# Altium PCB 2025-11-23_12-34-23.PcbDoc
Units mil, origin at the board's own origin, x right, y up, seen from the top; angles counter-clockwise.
Board outline 2370 x 1275 mil, 4 copper layers (Top Layer, MidLayer1, MidLayer2, Bottom Layer); 33 components, 22 nets, 92 pads, 279 vias.
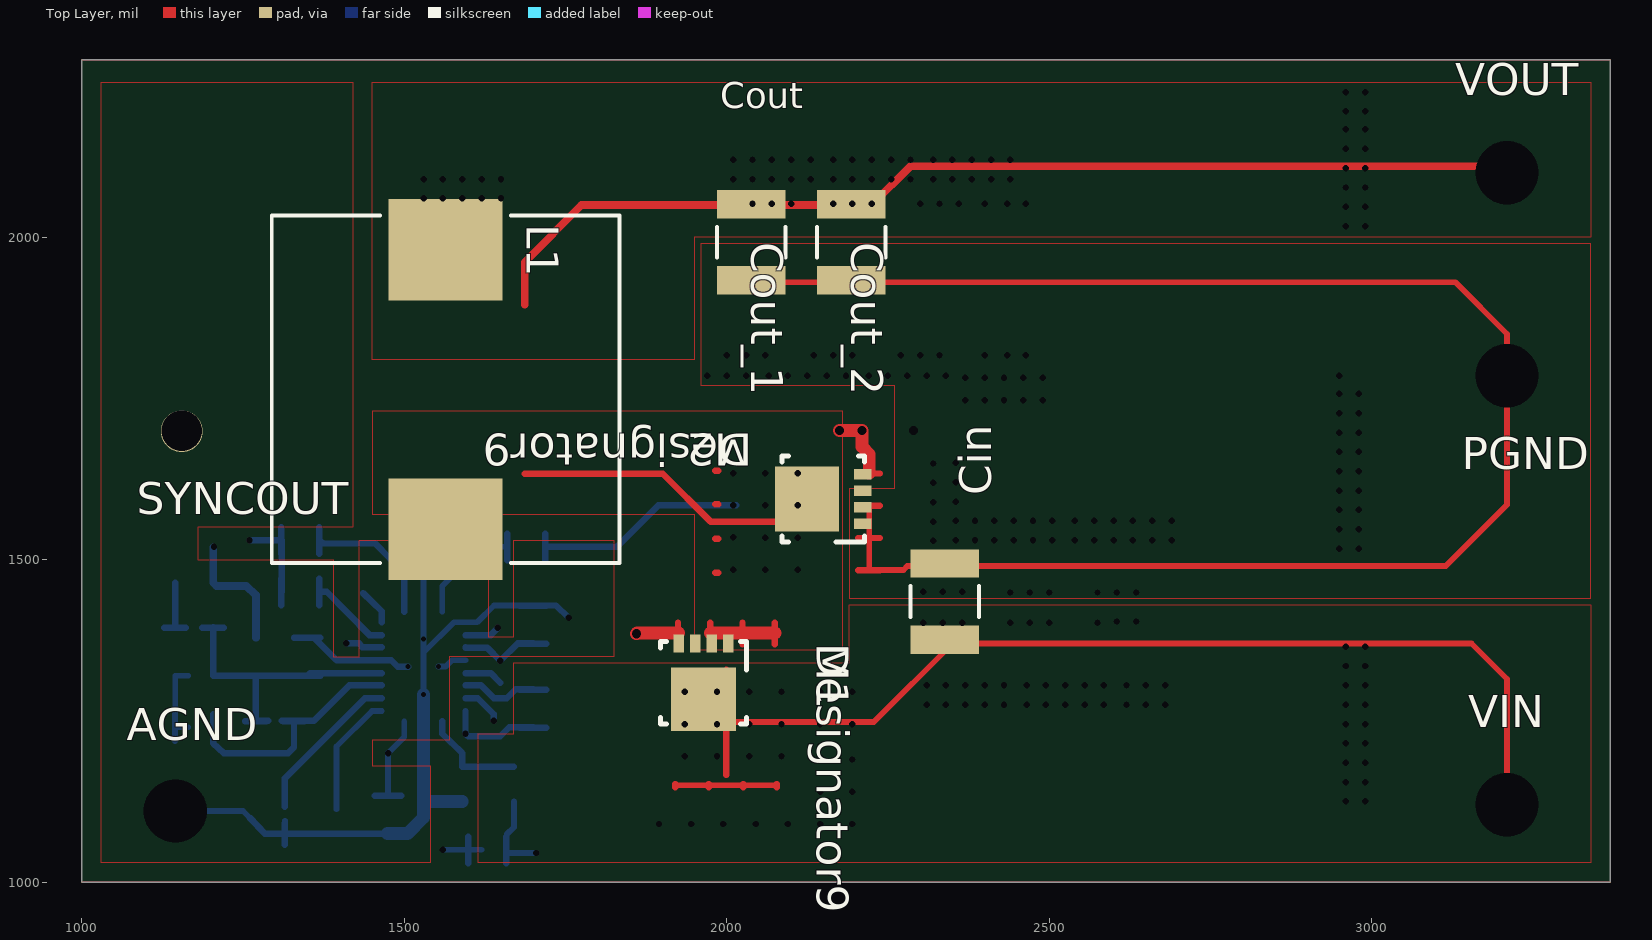
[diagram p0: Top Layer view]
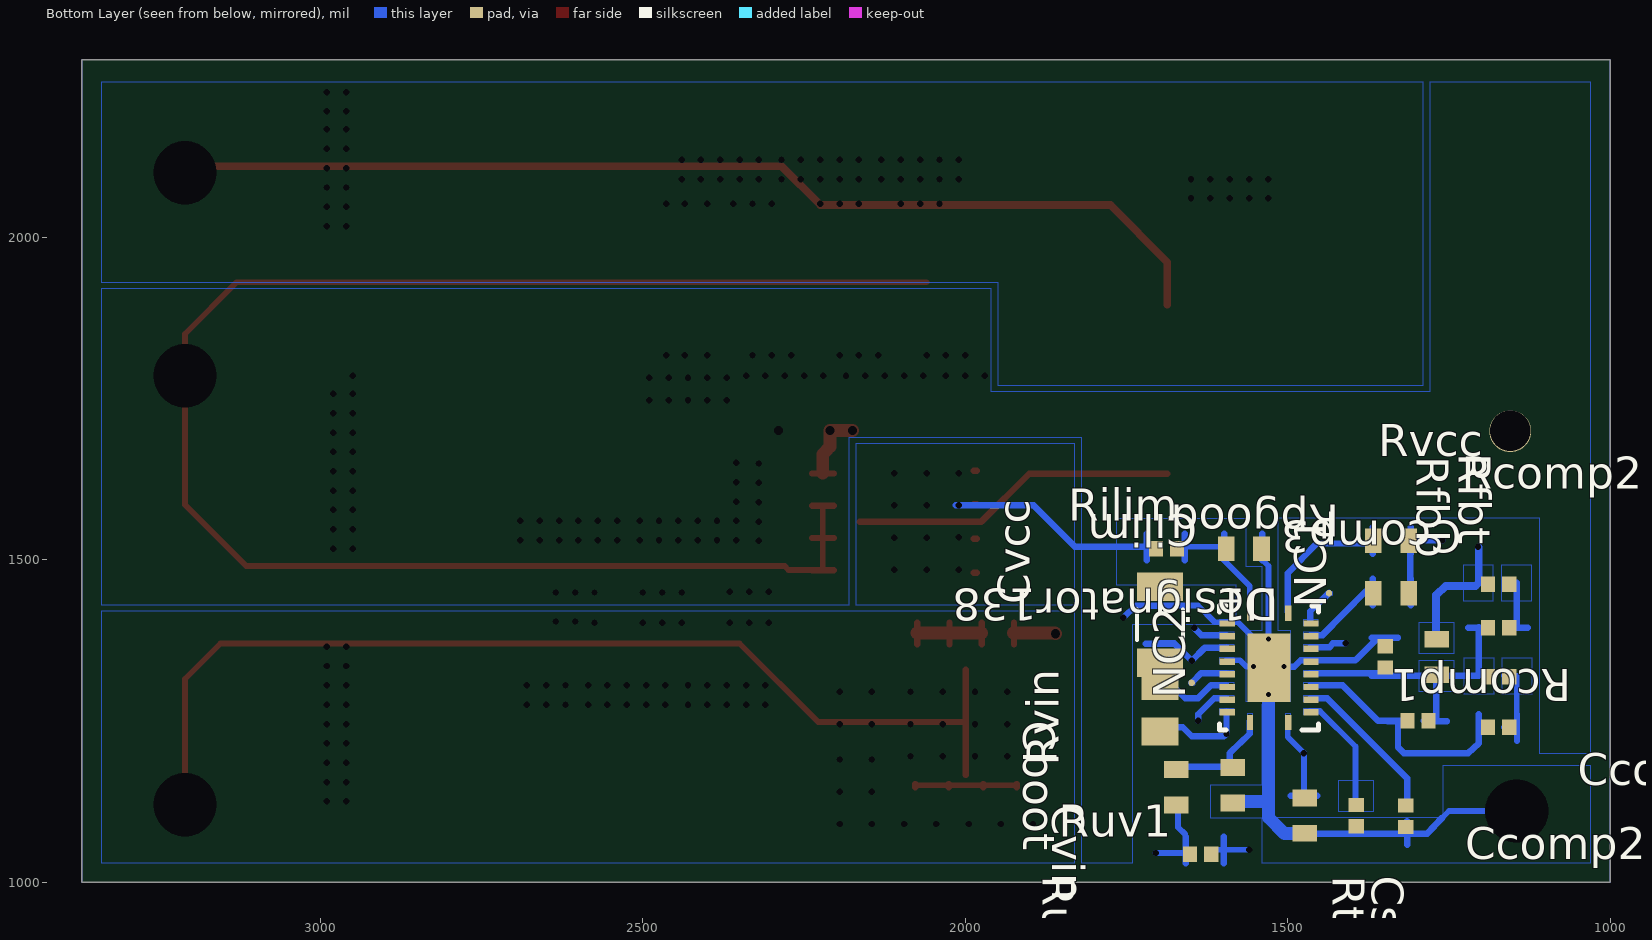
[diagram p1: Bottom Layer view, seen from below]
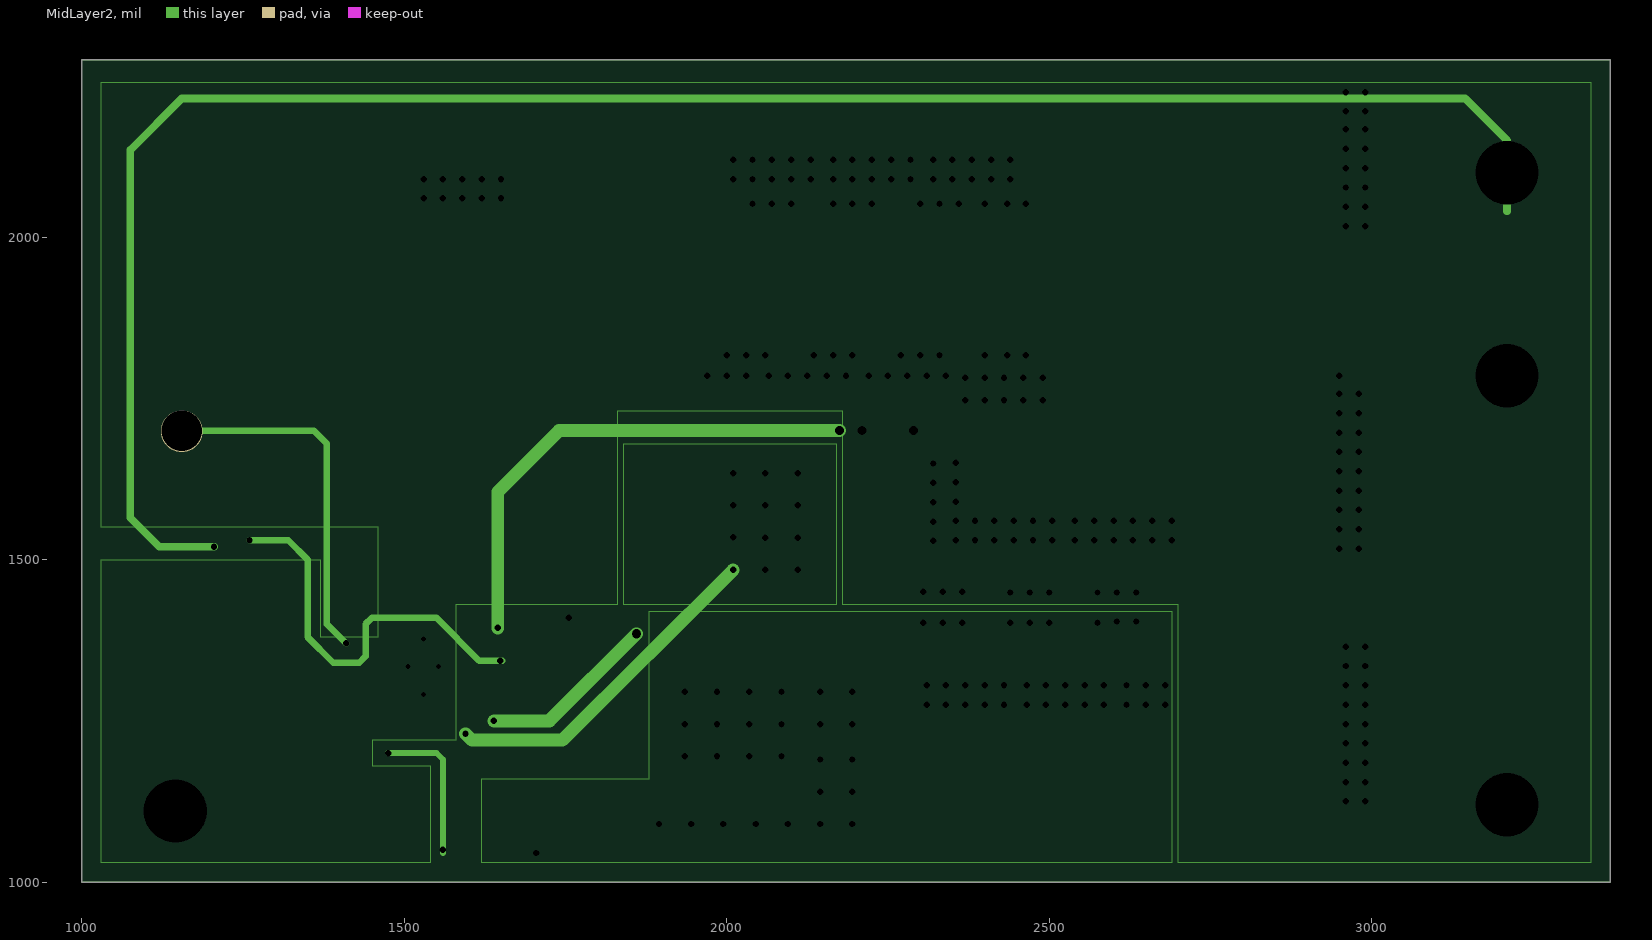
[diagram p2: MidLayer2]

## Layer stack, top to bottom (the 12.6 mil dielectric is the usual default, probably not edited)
Top Layer: signal copper 1.4
Dielectric: core 12.6, FR-4, Dk 4.8
MidLayer1: signal copper 1.4
Dielectric: prepreg 12.6, FR-4, Dk 4.8
MidLayer2: signal copper 1.4
Dielectric: core 12.6, FR-4, Dk 4.8
Bottom Layer: signal copper 1.4

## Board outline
1000,1000 3370,1000 3370,2275 1000,2275

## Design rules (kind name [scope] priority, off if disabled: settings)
PlaneConnect [All] p0: scope1count=1 scope1_0_kind=Board scope1_0_value=Board scope2count=1 scope2_0_kind=Board scope2_0_value=Board commentlength=0 planeconnectstyle=Direct reliefexpansion=20 reliefentries=4 reliefconductorwidth=10 reliefairgap=10
PlaneConnect [All] p1: planeconnectstyle=Direct reliefexpansion=20 reliefentries=4 reliefconductorwidth=10 reliefairgap=10
PolygonConnect [All] p0: scope1count=1 scope1_0_kind=Board scope1_0_value=Board scope2count=1 scope2_0_kind=Board scope2_0_value=Board commentlength=0 connectstyle=Direct reliefconductorwidth=10 reliefentries=4 polygonreliefangle="90 Angle"
PolygonConnect [All] p1: connectstyle=Direct reliefconductorwidth=10 reliefentries=4 polygonreliefangle="90 Angle"

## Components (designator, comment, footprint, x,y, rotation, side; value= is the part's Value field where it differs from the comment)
AGND "" TP-1502 1144,1109 r0 top
Cboot "" 0805 1698,1269 r90 bottom
Ccomp1 "" 0402 1173,1240 r0 bottom
Ccomp2 "" 0402 1298,1250 r0 bottom
Ccomp3 "" 0402 1173,1394 r180 bottom
Cilim "" 0603 1568,1517 r180 bottom
Cin "" 1210 2338,1435 r90 top
Cout_1 "" 1210 2038,1992 r270 top
Cout_2 "" 1210 2193,1992 r270 top
Css "" 0402 1317,1102 r90 bottom
Cvcc "" 1206 1698,1399 r270 bottom
Cvin "" 0603 1585,1150 r90 bottom
L1 "" SRP1270 1564,1764 r270 top
M1 "" DNH0008A 1964,1309 r270 top
M2 "" DNH0008A 2150,1594 r180 top
NC1 "" SMD_PAD1 1436,1448 r270 bottom
NC2 "" SMD_PAD1 1649,1309 r270 bottom
PGND "" TP-1502 3209,1785 r0 top
Rcomp1 "" 0402 1173,1318 r180 bottom
Rcomp2 "" 0402 1173,1462 r0 bottom
Rfbb "" 0402 1349,1349 r90 bottom
Rfbt "" 0603 1269,1349 r90 bottom
Rilim "" 0402 1688,1517 r0 bottom
Rpgood "" 0603 1340,1529 r180 bottom
Rt "" 0402 1394,1103 r90 bottom
Ruv1 "" 0402 1635,1043 r0 bottom
Ruv2 "" 0603 1474,1103 r90 bottom
Rvcc "" 0603 1340,1448 r0 bottom
Rvin "" 0603 1673,1147 r270 bottom
SYNCOUT "" TP-5012 1155,1699 r0 top
U1 "" RGY0020B 1529,1332 r180 bottom
VIN "" TP-1502 3209,1120 r0 top
VOUT "" TP-1502 3209,2100 r0 top

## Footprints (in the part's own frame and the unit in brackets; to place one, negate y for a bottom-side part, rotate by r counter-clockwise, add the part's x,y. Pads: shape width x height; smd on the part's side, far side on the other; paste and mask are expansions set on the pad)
0402 [mil]
  rect 22x24 smd: 1(16.5,0) 2(-16.5,0)
0603 [mil]
  rect 26x38 smd: 1(27.5,0) 2(-27.5,0)
0805 [mil]
  rect 44x57 smd: 1(35.5,0) 2(-35.5,0)
1206 [mil]
  rect 44x71 smd: 1(59,0) 2(-59,0)
  silkscreen extent -24,-36 24,36
1210 [mil]
  rect 44x106 smd: 1(-59,0) 2(59,0)
  silkscreen extent -24,-53 24,53
DNH0008A [mm]
  rect 0.7x0.4 smd: 1(-1.55,0.975) 2(-1.55,0.325) 3(-1.55,-0.325) 4(-1.55,-0.975) 5(1.55,-0.975) 6(1.55,-0.325) 7(1.55,0.325) 8(1.55,0.975)
  rect 2.51x2.55 smd: 9(0.645,0)
  silkscreen extent -1.62,-1.7 1.62,1.7
RGY0020B [mm]
  rect 0.25x0.6 smd: 1(0.75,-2.15) 10(0.75,2.15) 11(-0.75,2.15) 20(-0.75,-2.15)
  rect 0.6x0.25 smd: 2(1.65,-1.75) 3(1.65,-1.25) 4(1.65,-0.75) 5(1.65,-0.25) 6(1.65,0.25) 7(1.65,0.75) 8(1.65,1.25) 9(1.65,1.75) 12(-1.65,1.75) 13(-1.65,1.25) 14(-1.65,0.75) 15(-1.65,0.25) 16(-1.65,-0.25) 17(-1.65,-0.75) 18(-1.65,-1.25) 19(-1.65,-1.75)
  rect 1.7x2.7 smd: 21(0,0)
  silkscreen extent -1.95,-2.45 1.95,2.45
SMD_PAD1 [mil]
  round 10 smd: 1(0,0)
SRP1270 [mil]
  rect 157.5x177 smd: 1(-216.75,0) 2(216.75,0)
  silkscreen extent -270,-270 270,270
TP-1502 [mil]
  round 65 hole 32: 1(0,0)
TP-5012 [mil]
  round 65 hole 32: 1(0,0)

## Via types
v1: diameter 0, hole 10, Top Layer to Bottom Layer, 266 vias
v2: diameter 0, hole 8, Top Layer to Bottom Layer, 4 vias
v3: diameter 0, hole 14, Top Layer to Bottom Layer, 4 vias
v4: diameter 0, hole 98, Top Layer to Bottom Layer, 4 vias
v5: diameter 0, hole 63, Top Layer to Bottom Layer, 1 vias

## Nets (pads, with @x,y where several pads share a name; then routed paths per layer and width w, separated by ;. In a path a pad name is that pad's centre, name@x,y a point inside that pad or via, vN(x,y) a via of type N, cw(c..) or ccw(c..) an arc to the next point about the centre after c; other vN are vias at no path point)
0: AGND.1 Cilim.1 Cin.2 Cout_1.2 Cout_2.2 Css.2 Cvcc.2 Cvin.2 M2.1 M2.2 M2.3 PGND.1 Rfbb.1 Rt.2 Ruv2.2 U1.6 U1.12 U1.15 U1.21 | length 4255.3
  Top Layer w9: Cout_1.2@2060,1930 3130,1930 3210,1850 v4(3210,1785) 3210,1585 3115,1490 2370,1490 2280,1490 2274,1484 2221,1484 2221,1534 M2.2@2221,1584
  Top Layer w10: 2204,1483.5 2237,1483.5 ; 2204,1533.5 2237,1533.5 ; M2.2@2204,1583.5 2237,1583.5
  Bottom Layer w9: v4(1145,1110) 1250,1110 1260,1100 ; v2(1530,1291) 1530,1334 U1.21@1530,1356 ; Cilim.1@1540,1520 1540,1500 1530,1490 v2(1530,1377) U1.21@1530,1356 ; v2(1553,1334) 1564,1334 1574,1344 U1.15@1595,1344 ; v1(1755,1410) 1735,1429 1700,1429 1639,1429 1613,1403 1595,1403 1577,1403 U1.21@1530,1356
  Bottom Layer w10: 1260,1100 1284,1075 1315,1075 Ruv2.2@1474,1075 ; 1314.5,1058 Css.2@1314.5,1091 ; 1329,1378.5 1370,1378.5 ; 1350,1379 1360,1379 1395,1344 1465,1344 1480,1344 1490,1334 v2(1506,1334) ; 1454,1074.5 1495,1074.5 ; Cilim.1@1539.5,1499 1539.5,1540 ; 1679,1428.5 1720,1428.5
  Bottom Layer w20: Ruv2.2@1474,1075 1505,1075 1530,1100 1530,1130 ; v2(1530,1291) 1530,1130 ; Cvin.2@1590,1125 1534,1125 1530,1130
  other v1: 2440,1449 2470,1449 2500,1449 2575,1449 2605,1449 2635,1449 2305,1450 2335,1450 2365,1450 2950,1517 2980,1517 2320,1529 2355,1530 2385,1530 2415,1530 2445,1530 2475,1530 2505,1530 2540,1530 2570,1530 2600,1530 2630,1530 2660,1530 2690,1530 2950,1547 2980,1547 2320,1559 2355,1560 2385,1560 2415,1560 2445,1560 2475,1560 2505,1560 2540,1560 2570,1560 2600,1560 2630,1560 2660,1560 2690,1560 2950,1577 2980,1577 2320,1589 2355,1590 2950,1607 2980,1607 2320,1619 2355,1620 2950,1637 2980,1637 2320,1649 2355,1650 2950,1667 2980,1667 2950,1697 2980,1697 2950,1727 2980,1727 2370,1747 2400,1747 2430,1747 2460,1747 2490,1747 2950,1757 2980,1757 2370,1782 2400,1782 2430,1782 2460,1782 2490,1782 1970,1785 2000,1785 2030,1785 2065,1785 2095,1785 2125,1785 2155,1785 2185,1785 2220,1785 2250,1785 2280,1785 2310,1785 2340,1785 2950,1785 2000,1817 2030,1817 2060,1817 2135,1817 2165,1817 2195,1817 2270,1817 2300,1817 2330,1817 2400,1817 2435,1817 2464,1817
  other v3: 2290,1700
1: Cvcc.1 Rpgood.1 Rvcc.2 U1.14 | length 1005.8
  MidLayer2 w10: v1(1260,1530) 1320,1530 1350,1500 1350,1380 1390,1340 1430,1340 1440,1350 1440,1400 1450,1410 1550,1410 1616,1343 v1(1649,1343) 1652,1343
  Bottom Layer w10: v1(1260,1530) 1310,1530 Rvcc.2@1310,1450 ; Rvcc.2@1309.5,1429 1309.5,1470 ; 1309.5,1509 1309.5,1550 ; U1.14@1595,1364 1595,1363 1629,1363 v1(1649,1343) 1676,1370 1700,1370 ; 1679,1369.5 1720,1369.5
2: Cin.1 M1.5 M1.6 M1.7 M1.8 M1.9 Ruv1.1 Rvin.1 VIN.1 | length 1989.9
  Top Layer w9: 1921,1150 1973,1150 2026,1150 2078,1150 ; M1.8@2000,1248 2228,1248 2350,1370 2370,1370 3155,1370 3210,1315 v4(3210,1120)
  Top Layer w10: 1920.5,1147 1920.5,1152 ; 1972.5,1147 1972.5,1152 ; 1999.5,1166 M1.9@1999.5,1329 ; 2025.5,1147 2025.5,1152 ; 2077.5,1147 2077.5,1152
  Bottom Layer w9: Rvin.1@1670,1125 1670,1085 1659,1074 1659,1050 1659,1045 v1(1705,1045)
  Bottom Layer w10: 1658.5,1029 1658.5,1070
  other v1: 1895,1090 1945,1090 1995,1090 2045,1090 2095,1090 2145,1090 2195,1090 2960,1125 2990,1125 2145,1140 2195,1140 2960,1155 2990,1155 2960,1185 2990,1185 2145,1190 2195,1190 1935,1195 1985,1195 2035,1195 2085,1195 2960,1215 2990,1215 1935,1245 1985,1245 2035,1245 2085,1245 2145,1245 2195,1245 2960,1245 2990,1245 2310,1275 2340,1275 2370,1275 2400,1275 2430,1275 2465,1275 2495,1275 2525,1275 2555,1275 2585,1275 2620,1275 2650,1275 2680,1275 2960,1275 2990,1275 1935,1295 1985,1295 2035,1295 2085,1295 2145,1295 2195,1295 2310,1305 2340,1305 2370,1305 2400,1305 2430,1305 2465,1305 2495,1305 2525,1305 2555,1305 2585,1305 2620,1305 2650,1305 2680,1305 2960,1305 2990,1305 2960,1335 2990,1335 2960,1365 2990,1365 2305,1402 2335,1402 2365,1402 2440,1402 2470,1402 2500,1402 2575,1402 2605,1404 2635,1404
3: Ruv1.2 Ruv2.1 U1.1 | length 501.5
  MidLayer2 w9: v1(1475,1200) 1550,1200 1560,1190 v1(1560,1050) 1560,1045
  Bottom Layer w9: Ruv2.1@1475,1134 v1(1475,1200) 1500,1225 U1.1@1500,1249 ; v1(1560,1050) 1600,1050 Ruv1.2@1620,1050
  Bottom Layer w10: 1454,1133.5 1495,1133.5 ; 1599.5,1029 1599.5,1070
6: Cvin.1 Rvin.2 U1.20 | length 163.1
  Bottom Layer w10: U1.20@1559,1249 1559,1230 1590,1200 1590,1184 1590,1179 Rvin.2@1670,1179
7: Cout_1.1 Cout_2.1 L1.1 Rcomp2.1 Rfbt.1 VOUT.1 | length 4873.4
  Top Layer w12: 1687,1895 1687,1961 1775,2050 2060,2050 2165,2050 2225,2050 2285,2110 2350,2110 2410,2110 3200,2110 v4(3210,2100)
  MidLayer2 w12: v1(1205,1520) 1120,1520 1075,1565 1075,2135 1155,2215 3145,2215 3210,2150 v4(3210,2100) 3210,2040
  Bottom Layer w12: 1204,1519 1204,1464 1209,1459 1255,1459 1270,1445 Rfbt.1@1270,1379
  other v1: 2960,2017 2990,2017 2960,2047 2990,2047 2040,2052 2070,2052 2100,2052 2165,2052 2195,2052 2225,2052 2300,2052 2330,2052 2360,2052 2400,2052 2435,2052 2464,2052 1530,2060 1560,2060 1590,2060 1620,2060 1650,2060 2960,2077 2990,2077 1530,2090 1560,2090 1590,2090 1620,2090 1650,2090 2010,2090 2040,2090 2070,2090 2100,2090 2130,2090 2165,2090 2195,2090 2225,2090 2255,2090 2285,2090 2320,2090 2350,2090 2380,2090 2410,2090 2440,2090 2960,2107 2990,2107 2010,2120 2040,2120 2070,2120 2100,2120 2130,2120 2165,2120 2195,2120 2225,2120 2255,2120 2285,2120 2320,2120 2350,2120 2380,2120 2410,2120 2440,2120 2960,2137 2990,2137 2960,2167 2990,2167 2960,2195 2990,2195 2960,2225 2990,2225
8: Ccomp1.1 Ccomp2.1 U1.4 | length 452.4
  Bottom Layer w10: 1203.5,1219 1203.5,1260 ; 1204,1240 1204,1215 1220,1200 1320,1200 1329,1209 1329,1250 ; Ccomp2.1@1310,1250 1329,1250 ; Ccomp2.1@1312,1249.5 1345,1249.5 ; U1.4@1465,1305 1415,1305 1360,1250 1329,1250
9: Ccomp2.2 Ccomp3.2 Rcomp1.2 Rfbb.2 Rfbt.2 U1.5 | length 533.7
  Bottom Layer w10: Ccomp3.2@1187,1394.5 1220,1394.5 ; 1204,1395 1204,1320 1205,1320 Rfbt.2@1270,1320 ; 1253,1249.5 Ccomp2.2@1286,1249.5 ; Ccomp2.2@1289,1250 1270,1250 Rfbt.2@1270,1320 ; 1329,1319.5 1370,1319.5 ; U1.5@1465,1324 1354,1324 1350,1320 Rfbt.2@1270,1320
11: Cilim.2 Rilim.2 U1.11 | length 260.6
  Bottom Layer w9: U1.11@1559,1419 1559,1459 1599,1499 1599,1520 1660,1520
  Bottom Layer w10: Cilim.2@1598.5,1499 1598.5,1540 ; 1659.5,1499 1659.5,1540
14: Cboot.2 L1.2 M1.1 M1.2 M1.3 M2.5 M2.6 M2.7 M2.8 M2.9 Rilim.1 U1.19 | length 1888.8
  Top Layer w10: 1687,1633 1901,1633 1975,1559 M2.8@2083,1559 ; M1.2@1974.5,1369 1974.5,1402 ; 1982,1479.5 1987,1479.5 ; 1982,1532.5 1987,1532.5 ; 1982,1585.5 1987,1585.5 ; 1982,1637.5 1987,1637.5 ; 2001,1558.5 M2.9@2164,1558.5 ; 2024.5,1369 2024.5,1402 ; 2074.5,1369 2074.5,1402
  Top Layer w20: 1975,1386 2025,1386 2075,1386
  MidLayer2 w20: v1(1595,1230) 1605,1220 1745,1220 v1(2010,1484)
  Bottom Layer w10: U1.19@1595,1265 v1(1595,1230) 1599,1226 1649,1226 1663,1240 Cboot.2@1700,1240 ; Cboot.2@1679,1239.5 Cboot.2@1720,1239.5 ; 1718.5,1499 1718.5,1540 ; 1719,1520 1830,1520 1894,1584 v1(2010,1584) 2015,1584
  other v1: 2060,1484 2110,1484 2060,1534 2110,1534 2010,1535 2060,1584 2110,1584 2010,1634 2060,1634 2110,1634
18: Ccomp1.2 Rcomp1.1 | length 161
  Bottom Layer w9: Ccomp1.2@1165,1240 1145,1240 1145,1320 Rcomp1.1@1165,1320
  Bottom Layer w10: 1144.5,1219 1144.5,1260
19: Ccomp3.1 Rcomp2.2 | length 102
  Bottom Layer w10: 1128,1394.5 Ccomp3.1@1161,1394.5 ; 1145,1395 1145,1464
20: Rvcc.1 U1.8 | length 165
  Bottom Layer w10: Rvcc.1@1368.5,1429 1368.5,1470 ; Rvcc.1@1369,1450 1380,1450 1446,1383 U1.8@1465,1383
22: NC2.1 U1.16 | length 60.2
  Bottom Layer w10: U1.16@1595,1324 1634,1324 NC2.1
23: NC1.1 U1.9 | length 57.3
  Bottom Layer w10: NC1.1 1465,1420 U1.9@1465,1403
27: Rt.1 U1.2 | length 189.8
  Bottom Layer w9: Rt.1@1395,1113 1395,1134 1395,1210 1450,1265 U1.2@1465,1265
28: Cboot.1 U1.17 | length 160.1
  Bottom Layer w10: U1.17@1595,1305 1619,1305 1639,1285 1659,1285 1673,1299 Cboot.1@1700,1299 ; Cboot.1@1679,1298.5 Cboot.1@1720,1298.5
30: Css.1 U1.3 | length 261.4
  Bottom Layer w10: Css.1@1314.5,1117 1314.5,1150 ; 1315,1134 1315,1161 1439,1285 U1.3@1465,1285
36: M1.4 U1.18 | length 439.7
  Top Layer w10: M1.4@1924.5,1369 1924.5,1402
  Top Layer w20: v3(1860,1385) 1861,1386 1925,1386
  MidLayer2 w20: v1(1639,1250) 1725,1250 v3(1860,1385)
  Bottom Layer w10: U1.18@1595,1285 1614,1285 1638,1261 1639,1260 v1(1639,1250)
37: M2.4 U1.13 | length 973.2
  Top Layer w10: M2.4@2204,1633.5 2237,1633.5
  Top Layer w20: v3(2175,1700) v3(2210,1700) 2210,1675 2221,1663 M2.4@2221,1634
  MidLayer2 w20: v1(1645,1394) 1645,1605 1740,1700 v3(2175,1700)
  Bottom Layer w10: U1.13@1595,1383 1634,1383 v1(1645,1394)
38: SYNCOUT.1 U1.7 | length 623.5
  MidLayer2 w10: SYNCOUT.1@1145,1700 v5(1155,1700) 1360,1700 1380,1680 1380,1400 v1(1410,1370)
  Bottom Layer w10: v1(1410,1370) 1430,1370 1435,1364 U1.7@1465,1364
39: Rpgood.2 U1.10 | length 253.4
  Bottom Layer w10: 1368.5,1509 1368.5,1550 ; Rpgood.2@1369,1530 1374,1525 1455,1525 1500,1479 U1.10@1500,1419

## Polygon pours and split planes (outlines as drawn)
7 on Top Layer " " (solid, pour order 31): 1450,2240 3340,2240 3340,2000 1950,2000 1950,1810 1450,1810
2 on Top Layer " " (solid, pour order 32): 3340,1030 1615,1030 1615,1230 1670,1230 1670,1340 2190,1340 2190,1430 3340,1430
14 on Top Layer " " (solid, pour order 33): 2180,1360 2180,1730 1450,1730 1450,1570 1950,1570 1950,1360
0 on Top Layer " " (solid, pour order 41): 1030,2240 1420,2240 1420,1550 1180,1550 1180,1500 1280,1500 1390,1500 1390,1349 1430,1349 1430,1530 1630,1530 1630,1380 1670,1380 1670,1530 1825,1530 1825,1349 1570,1349 1570,1220 1450,1220 1450,1180 1540,1180 1540,1030 1030,1030
0 on Top Layer " " (solid, pour order 42): 1960,1990 1960,1770 2260,1770 2260,1610 2190,1610 2190,1440 3340,1440 3340,1990
1 on Bottom Layer " " (solid, pour order 0): 1583,1359 1583,1368 1606,1368 1606,1359
37 on Bottom Layer " " (solid, pour order 1): 1583,1378 1583,1387 1606,1387 1606,1378
11 on Bottom Layer " " (solid, pour order 2): 1554,1407 1554,1430 1563,1430 1563,1407
28 on Bottom Layer " " (solid, pour order 3): 1583,1300 1583,1309 1606,1309 1606,1300
36 on Bottom Layer " " (solid, pour order 4): 1583,1280 1583,1289 1606,1289 1606,1280
22 on Bottom Layer " " (solid, pour order 5): 1583,1319 1583,1328 1606,1328 1606,1319
14 on Bottom Layer " " (solid, pour order 6): 1583,1260 1583,1269 1606,1269 1606,1260
6 on Bottom Layer " " (solid, pour order 7): 1554,1238 1554,1261 1563,1261 1563,1238
39 on Bottom Layer " " (solid, pour order 8): 1495,1407 1495,1430 1504,1430 1504,1407
23 on Bottom Layer " " (solid, pour order 9): 1453,1398 1453,1407 1476,1407 1476,1398
20 on Bottom Layer " " (solid, pour order 10): 1453,1378 1453,1387 1476,1387 1476,1378
9 on Bottom Layer " " (solid, pour order 11): 1453,1319 1453,1328 1476,1328 1476,1319
38 on Bottom Layer " " (solid, pour order 12): 1453,1359 1453,1368 1476,1368 1476,1359
8 on Bottom Layer " " (solid, pour order 13): 1453,1300 1453,1309 1476,1309 1476,1300
3 on Bottom Layer " " (solid, pour order 14): 1495,1238 1495,1261 1504,1261 1504,1238
30 on Bottom Layer " " (solid, pour order 15): 1453,1280 1453,1289 1476,1289 1476,1280
27 on Bottom Layer " " (solid, pour order 16): 1453,1260 1453,1269 1476,1269 1476,1260
7 on Bottom Layer " " (solid, pour order 17): 1181,1436 1181,1491 1228,1491 1228,1436
19 on Bottom Layer " " (solid, pour order 18): 1122,1436 1122,1491 1169,1491 1169,1436
9 on Bottom Layer " " (solid, pour order 19): 1242,1296 1242,1343 1297,1343 1297,1296
7 on Bottom Layer " " (solid, pour order 20): 1242,1355 1242,1402 1297,1402 1297,1355
18 on Bottom Layer " " (solid, pour order 21): 1121,1292 1121,1347 1168,1347 1168,1292
9 on Bottom Layer " " (solid, pour order 22): 1180,1292 1180,1347 1227,1347 1227,1292
27 on Bottom Layer " " (solid, pour order 23): 1367,1110 1367,1157 1422,1157 1422,1110
23 on Bottom Layer " " (solid, pour order 24): 1441,1448 1440,1448 1440,1449 1440,1450 1439,1451 1438,1452 1437,1452 1436,1452 1436,1453 1435,1452 1434,1452 1433,1452 1432,1451 1431,1450 1431,1449 1431,1448 1431,1447 1431,1446 1431,1445 1432,1444 1433,1443 1434,1443 1435,1443 1436,1443 1437,1443 1438,1443 1439,1444 1440,1445 1440,1446 1440,1447 1441,1448
22 on Bottom Layer " " (solid, pour order 25): 1654,1309 1653,1309 1653,1310 1653,1311 1652,1312 1651,1313 1650,1313 1649,1313 1649,1314 1648,1313 1647,1313 1646,1313 1645,1312 1644,1311 1644,1310 1644,1309 1644,1308 1644,1307 1644,1306 1645,1305 1646,1304 1647,1304 1648,1304 1649,1304 1650,1304 1651,1304 1652,1305 1653,1306 1653,1307 1653,1308 1654,1309
2 on Bottom Layer " " (solid, pour order 28): 3340,1030 1830,1030 1830,1420 3340,1420
14 on Bottom Layer " " (solid, pour order 29): 1830,1680 2170,1680 2170,1430 1830,1430
7 on Bottom Layer " " (solid, pour order 30): 1950,1770 1290,1770 1290,2240 3340,2240 3340,1930 1950,1930
0 on Bottom Layer " " (solid, pour order 34): 1583,1398 1583,1407 1606,1407 1606,1398
0 on Bottom Layer " " (solid, pour order 35): 1583,1339 1583,1348 1606,1348 1606,1339
0 on Bottom Layer " " (solid, pour order 36): 1453,1339 1453,1348 1476,1348 1476,1339
0 on Bottom Layer " " (solid, pour order 39): 1820,1030 1740,1030 1740,1400 1620,1400 1580,1400 1580,1460 1765,1460 1765,1564 1565,1564 1565,1490 1540,1490 1540,1390 1565,1390 1565,1280 1495,1280 1495,1390 1515,1390 1515,1565 1110,1565 1110,1200 1030,1200 1030,2240 1280,2240 1280,1760 1960,1760 1960,1920 3340,1920 3340,1430 2180,1430 2180,1690 1820,1690
0 on Bottom Layer " " (solid, pour order 40): 1520,1100 1520,1275 1540,1275 1540,1150 1620,1150 1620,1100 1540,1100 1540,1030 1030,1030 1030,1180 1260,1180 1260,1100
14 on MidLayer2 " " (solid, pour order 26): 1840,1680 2170,1680 2170,1430 1840,1430
2 on MidLayer2 " " (solid, pour order 27): 2690,1030 1620,1030 1620,1160 1880,1160 1880,1420 2690,1420
0 on MidLayer1 " " (solid, pour order 37): 3050,1030 1720,1030 1720,1420 1610,1420 1610,1250 1450,1250 1450,1180 1500,1180 1500,1200 1670,1200 1670,1030 1610,1030 1610,1130 1540,1130 1540,1030 1030,1030 1030,1500 1390,1500 1390,1380 1460,1380 1460,1560 1030,1560 1030,2240 3340,2240 3340,1030
0 on MidLayer2 " " (solid, pour order 38): 1030,2240 3340,2240 3340,1030 2700,1030 2700,1430 2180,1430 2180,1730 1830,1730 1830,1430 1580,1430 1580,1220 1450,1220 1450,1180 1540,1180 1540,1030 1030,1030 1030,1500 1370,1500 1370,1380 1460,1380 1460,1550 1030,1550

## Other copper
Multi-Layer:
  the board outline again, w1

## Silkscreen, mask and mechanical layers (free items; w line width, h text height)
Top Overlay:
  text "Cout" at 1990,2200 h40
